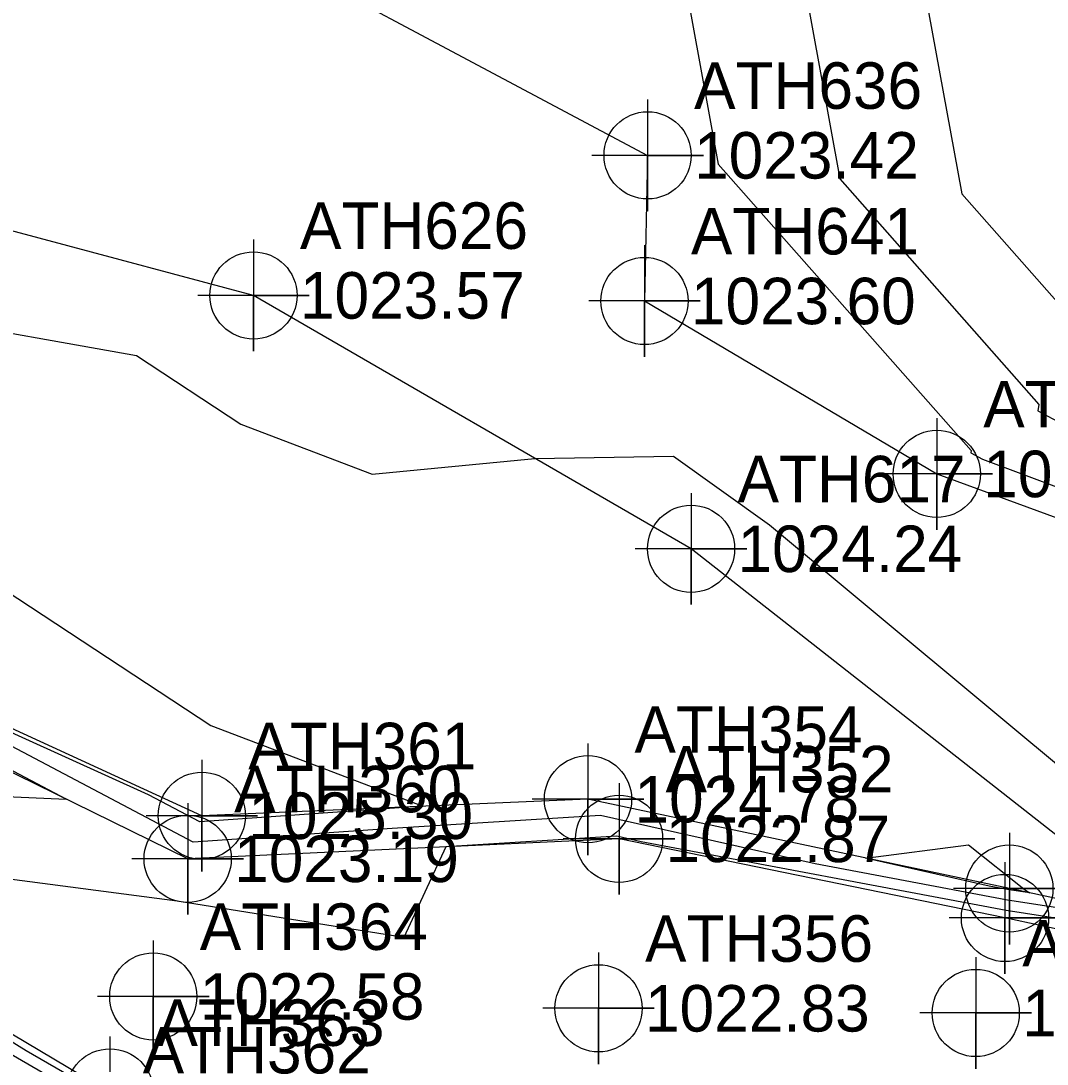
# Model space of a CAD drawing. Extents: x 1213164 to 1213550, y 766120 to 766870.
# Drawn here: x 1213249.2 to 1213304.4, y 766483.4 to 766539.5 of the extents above; entities that cross this region are included whole.
import ezdxf

# ---------------------------------------------------------------- set-up
doc = ezdxf.new("R2010")
doc.units = 0
for name, color, linetype in [('Default', 7, 'Continuous'), ('Exist DTM Breakline', 7, 'Continuous'), ('Exist DTM Breakline Cogo Elevation', 7, 'Continuous'), ('Exist DTM Breakline Cogo Number', 7, 'Continuous'), ('Exist DTM Breakline Cogo Point CELL', 7, 'Continuous'), ('Exist DTM Drainline Cogo Elevation', 7, 'Continuous'), ('Exist DTM Drainline Cogo Number', 7, 'Continuous'), ('Exist DTM Drainline Cogo Point CELL', 7, 'Continuous'), ('Exist DTM Regular Point Underwater CELL', 7, 'Continuous'), ('Exist DTM Regular Point Underwater Cogo Elevation', 7, 'Continuous'), ('Exist DTM Regular Point Underwater Cogo Number', 7, 'Continuous'), ('Exist Environmental Wetland Boundary Cogo Elevation', 7, 'Continuous'), ('Exist Environmental Wetland Boundary Cogo Number', 7, 'Continuous'), ('Exist Environmental Wetland Boundary Cogo Point CELL', 7, 'Continuous'), ('Exist Hydro Stream or Body of Water', 7, 'Continuous')]:
    doc.layers.add(name, color=color, linetype=linetype)

msp = doc.modelspace()

# ---------------------------------------------------------------- linework, layer by layer
at = {"layer": 'Default'}
for points in [[(1213289.1192499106, 766553.4423376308), (1213293.2180259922, 766531.0141339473), (1213303.9205507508, 766518.8947595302), (1213303.869917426, 766518.5396103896), (1213305.740823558, 766517.5401958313)], [(1213296.7797298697, 766546.5573491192), (1213299.7671241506, 766530.2105455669), (1213307.5676628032, 766521.3773355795)], [(1213284.8018533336, 766542.0342177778), (1213286.6689278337, 766531.8177223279), (1213300.2734386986, 766516.412183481), (1213300.2564264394, 766516.2928571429), (1213300.8850310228, 766515.9570644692), (1213316.7434999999, 766510.0117254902)], [(1213223.4522835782, 766501.0990636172), (1213225.7273167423, 766500.417861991), (1213227.7784803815, 766498.6388193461), (1213228.6049630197, 766498.694247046), (1213251.6057317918, 766497.6713433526), (1213236.8667792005, 766505.4526248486), (1213231.2971667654, 766507.9754647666), (1213229.1962276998, 766509.0414330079), (1213228.7504468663, 766509.2435858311), (1213227.5175, 766526.7724230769)], [(1213302.237526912, 766492.2400042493), (1213291.8869665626, 766494.1944431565), (1213280.3513956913, 766496.7988423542), (1213269.1433913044, 766496.1008197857), (1213258.4343595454, 766495.3541406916), (1213246.4477447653, 766501.6823531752), (1213231.430104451, 766508.4848197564), (1213230.1335065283, 766509.1426837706), (1213229.0183851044, 766509.6483693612), (1213227.82, 766526.6858411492), (1213231.7452264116, 766525.9756047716), (1213232.384419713, 766525.6060891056), (1213255.3908439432, 766521.5189148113), (1213260.9941407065, 766517.8376878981), (1213268.0661230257, 766515.1395785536), (1213276.8144201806, 766515.9927831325), (1213284.2753601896, 766516.1182322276), (1213289.4289636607, 766512.4142018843), (1213289.74796495, 766512.1484445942), (1213306.4730306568, 766498.23270073), (1213311.3375821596, 766496.8069984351), (1213311.4064809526, 766491.6109761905), (1213312.8713956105, 766490.6043669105), (1213302.237526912, 766492.2400042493)], [(1213231.070785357, 766509.2439345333), (1213229.2863233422, 766510.0531528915), (1213228.8199999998, 766516.6828838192), (1213230.3474094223, 766516.4065120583), (1213231.9253504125, 766515.4943092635), (1213240.6597993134, 766513.9426028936), (1213259.385570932, 766501.6402356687), (1213270.7925038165, 766497.2882519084), (1213258.7948522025, 766496.451724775), (1213256.0287103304, 766497.912081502), (1213231.5630421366, 766508.9941747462), (1213231.070785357, 766509.2439345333)], [(1213313.6045501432, 766489.9197163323), (1213302.1546657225, 766491.680868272), (1213282.5294097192, 766495.3865965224), (1213281.2294829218, 766495.6800825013), (1213272.0173512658, 766495.1063607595), (1213269.7741866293, 766490.2333481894), (1213257.5716084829, 766492.1833588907), (1213233.3693369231, 766495.35514)], [(1213232.0588285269, 766494.9257890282), (1213249.4618614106, 766484.155977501), (1213253.8233532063, 766481.6289549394), (1213257.2612087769, 766480.3647865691), (1213273.0448975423, 766474.7949686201), (1213274.015282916, 766474.7610461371), (1213298.2993294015, 766477.708404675), (1213299.2070299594, 766477.7805484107), (1213310.3054437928, 766477.1165972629)], [(1213302.3203881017, 766492.7991402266), (1213301.244523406, 766493.0022897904), (1213294.5989411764, 766494.5026705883), (1213300.1387571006, 766495.2207557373), (1213303.1952337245, 766492.7874919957), (1213303.4257006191, 766492.6291277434), (1213302.3203881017, 766492.7991402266)], [(1213241.159022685, 766488.3053824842), (1213253.5675473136, 766481.1159566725), (1213263.3483098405, 766477.5193743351), (1213272.7314759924, 766474.2082011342), (1213279.123008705, 766473.9847675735), (1213297.907950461, 766476.2646989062), (1213302.490552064, 766476.6289225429), (1213309.1317715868, 766476.2316184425)]]:
    msp.add_lwpolyline(points, dxfattribs=at)
at = {"layer": 'Exist DTM Breakline'}
msp.add_lwpolyline([(1213319.115, 766489.2660000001), (1213302.33, 766492.8640000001), (1213279.67, 766497.667), (1213258.903, 766496.781), (1213229.457, 766510.311)], dxfattribs=at)
at = {"layer": 'Exist DTM Breakline Cogo Point CELL'}
for points in [[(1213279.67, 766500.667), (1213279.67, 766494.667), (1213279.67, 766497.667), (1213282.67, 766497.667), (1213276.67, 766497.667)], [(1213258.903, 766499.781), (1213258.903, 766493.781), (1213258.903, 766496.781), (1213261.903, 766496.781), (1213255.903, 766496.781)], [(1213302.33, 766495.8640000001), (1213302.33, 766489.8640000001), (1213302.33, 766492.8640000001), (1213305.33, 766492.8640000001), (1213299.33, 766492.8640000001)]]:
    msp.add_lwpolyline(points, dxfattribs=at)
for centre in [(1213279.67, 766497.667), (1213258.903, 766496.781), (1213302.33, 766492.8640000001)]:
    msp.add_circle(centre, 2.344041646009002, dxfattribs=at)
at = {"layer": 'Exist DTM Drainline Cogo Point CELL'}
for points in [[(1213281.341, 766498.5380000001), (1213281.341, 766492.5380000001), (1213281.341, 766495.5380000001), (1213284.341, 766495.5380000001), (1213278.341, 766495.5380000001)], [(1213258.142, 766497.464), (1213258.142, 766491.464), (1213258.142, 766494.464), (1213261.142, 766494.464), (1213255.142, 766494.464)], [(1213302.0960000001, 766494.285), (1213302.0960000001, 766488.285), (1213302.0960000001, 766491.285), (1213305.0960000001, 766491.285), (1213299.0960000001, 766491.285)], [(1213253.962, 766484.907), (1213253.962, 766478.907), (1213253.962, 766481.907), (1213256.962, 766481.907), (1213250.962, 766481.907)]]:
    msp.add_lwpolyline(points, dxfattribs=at)
for centre in [(1213281.341, 766495.5380000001), (1213258.142, 766494.464), (1213302.0960000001, 766491.285), (1213253.962, 766481.907)]:
    msp.add_circle(centre, 2.344041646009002, dxfattribs=at)
at = {"layer": 'Exist DTM Regular Point Underwater CELL'}
for points in [[(1213256.2920000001, 766490.067), (1213256.2920000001, 766484.067), (1213256.2920000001, 766487.067), (1213259.2920000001, 766487.067), (1213253.2920000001, 766487.067)], [(1213280.237, 766489.4280000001), (1213280.237, 766483.4280000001), (1213280.237, 766486.4280000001), (1213283.237, 766486.4280000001), (1213277.237, 766486.4280000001)], [(1213300.523, 766489.1780000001), (1213300.523, 766483.1780000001), (1213300.523, 766486.1780000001), (1213303.523, 766486.1780000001), (1213297.523, 766486.1780000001)]]:
    msp.add_lwpolyline(points, dxfattribs=at)
for centre in [(1213256.2920000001, 766487.067), (1213280.237, 766486.4280000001), (1213300.523, 766486.1780000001)]:
    msp.add_circle(centre, 2.344041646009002, dxfattribs=at)
at = {"layer": 'Exist Environmental Wetland Boundary Cogo Point CELL'}
for points in [[(1213282.877, 766535.283), (1213282.877, 766529.283), (1213282.877, 766532.283), (1213285.877, 766532.283), (1213279.877, 766532.283)], [(1213261.681, 766527.7540000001), (1213261.681, 766521.7540000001), (1213261.681, 766524.7540000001), (1213264.681, 766524.7540000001), (1213258.681, 766524.7540000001)], [(1213282.707, 766527.453), (1213282.707, 766521.453), (1213282.707, 766524.453), (1213285.707, 766524.453), (1213279.707, 766524.453)], [(1213298.428, 766518.156), (1213298.428, 766512.156), (1213298.428, 766515.156), (1213301.428, 766515.156), (1213295.428, 766515.156)], [(1213285.214, 766514.13), (1213285.214, 766508.13), (1213285.214, 766511.13), (1213288.214, 766511.13), (1213282.214, 766511.13)]]:
    msp.add_lwpolyline(points, dxfattribs=at)
for centre in [(1213282.877, 766532.283), (1213261.681, 766524.7540000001), (1213282.707, 766524.453), (1213298.428, 766515.156), (1213285.214, 766511.13)]:
    msp.add_circle(centre, 2.344041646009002, dxfattribs=at)
at = {"layer": 'Exist Hydro Stream or Body of Water'}
for points in [[(1213231.611, 766558.456), (1213254.919, 766547.1630000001), (1213282.877, 766532.283), (1213282.707, 766524.453), (1213298.428, 766515.156), (1213316.5250000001, 766508.528)], [(1213309.3190000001, 766492.246), (1213285.214, 766511.13), (1213261.681, 766524.7540000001), (1213227.09, 766533.988)], [(1213319.329, 766487.569), (1213302.0960000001, 766491.285), (1213281.341, 766495.5380000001), (1213258.142, 766494.464), (1213228.572, 766508.974)], [(1213298.396, 766478.0650000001), (1213273.101, 766474.9), (1213253.962, 766481.907), (1213225.147, 766499.034)]]:
    msp.add_lwpolyline(points, dxfattribs=at)

# ---------------------------------------------------------------- texts
at = {"layer": 'Exist DTM Breakline Cogo Elevation'}
for s, p in [('1024.78', (1213282.17, 766496.417)), ('1025.30', (1213261.403, 766495.531))]:
    msp.add_text(s, height=2.5, dxfattribs=at).set_placement(p)
at = {"layer": 'Exist DTM Breakline Cogo Number'}
for s, p in [('ATH354', (1213282.17, 766500.167)), ('ATH361', (1213261.403, 766499.281)), ('ATH362', (1213255.724, 766482.927))]:
    msp.add_text(s, height=2.5, dxfattribs=at).set_placement(p)
at = {"layer": 'Exist DTM Drainline Cogo Elevation'}
for s, p in [('1022.87', (1213283.841, 766494.2880000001)), ('1023.19', (1213260.642, 766493.214))]:
    msp.add_text(s, height=2.5, dxfattribs=at).set_placement(p)
at = {"layer": 'Exist DTM Drainline Cogo Number'}
for s, p in [('ATH352', (1213283.841, 766498.0380000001)), ('ATH360', (1213260.642, 766496.964)), ('ATH363', (1213256.462, 766484.407))]:
    msp.add_text(s, height=2.5, dxfattribs=at).set_placement(p)
at = {"layer": 'Exist DTM Regular Point Underwater Cogo Elevation'}
for s, p in [('1022.58', (1213258.7920000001, 766485.817)), ('1022.83', (1213282.737, 766485.1780000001)), ('1022.20', (1213303.023, 766484.9280000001))]:
    msp.add_text(s, height=2.5, dxfattribs=at).set_placement(p)
at = {"layer": 'Exist DTM Regular Point Underwater Cogo Number'}
for s, p in [('ATH364', (1213258.7920000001, 766489.567)), ('ATH356', (1213282.737, 766488.9280000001)), ('ATH349', (1213303.023, 766488.6780000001))]:
    msp.add_text(s, height=2.5, dxfattribs=at).set_placement(p)
at = {"layer": 'Exist Environmental Wetland Boundary Cogo Elevation'}
for s, p in [('1023.42', (1213285.377, 766531.033)), ('1023.57', (1213264.181, 766523.5040000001)), ('1023.60', (1213285.207, 766523.203)), ('1023.49', (1213300.928, 766513.906)), ('1024.24', (1213287.714, 766509.88))]:
    msp.add_text(s, height=2.5, dxfattribs=at).set_placement(p)
at = {"layer": 'Exist Environmental Wetland Boundary Cogo Number'}
for s, p in [('ATH636', (1213285.377, 766534.783)), ('ATH626', (1213264.181, 766527.2540000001)), ('ATH641', (1213285.207, 766526.953)), ('ATH642', (1213300.928, 766517.656)), ('ATH617', (1213287.714, 766513.63))]:
    msp.add_text(s, height=2.5, dxfattribs=at).set_placement(p)

doc.saveas('drawing.dxf')
